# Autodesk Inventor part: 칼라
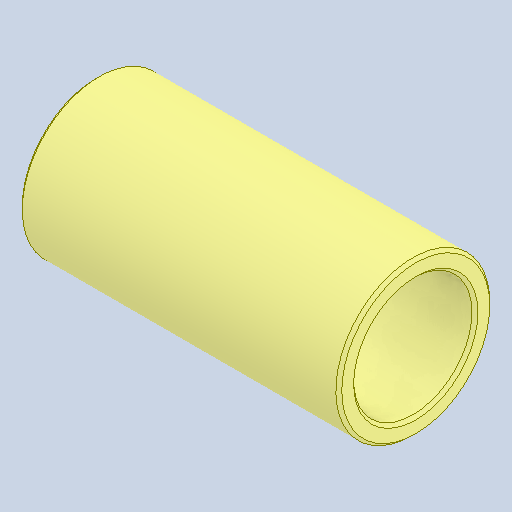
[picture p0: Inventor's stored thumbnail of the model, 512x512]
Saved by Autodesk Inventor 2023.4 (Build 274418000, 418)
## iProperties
Created: 2024-09
Part Number: 칼라
Material: 강철, 연강
Document SubType Name: Modeling
Designer: 11
Density: 7.85 g/cm^3
Appearance: 기본값
Author: jhkim
Sending System: Autodesk Inventor 2025
Preprocessor: ST-DEVELOPER v20
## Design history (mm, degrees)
node "칼라1"
node "솔리드2"
node "솔리드1"
